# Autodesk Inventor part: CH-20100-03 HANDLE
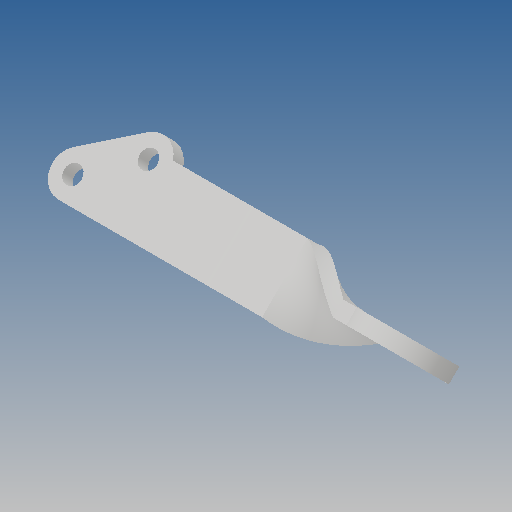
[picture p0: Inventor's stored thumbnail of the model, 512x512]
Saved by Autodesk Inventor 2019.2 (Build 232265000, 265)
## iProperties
Created: 2012-09
Part Number: CH-20100-03 HANDLE
Material: Ogólny
Document SubType Name: Modeling
Designer: CADENGINEERING4
Density: 1 g/cm^3
Appearance: Domyślna
Author: CADENGINEERING4
Revision Number: ÈÎºÎ
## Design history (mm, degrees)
feature "ÇÐ³ý-À­Éì3"
node "Bryła1"
